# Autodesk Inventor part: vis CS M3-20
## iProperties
Shininess: 20.0
Angle Display Precision: 2
Document Length Units: 11269
Document Angle Units: 11279
Document Time Units: 11290
Document Mass Units: 11283
Document Length Units Precision: 3
Document Angle Units Precision: 2
Compacted: True
Created: 2002-04
Part Number: vis CS M3-20
Material: Par défaut
Document SubType Name: Modélisation
Designer: thchene
Density: 0.0
Volumn: 0.0
Area: 0.0
PropertySet Name: Model Information
Control State: 0
Master: False
Checked Out: False
Author: thchene
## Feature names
1. Révolution1 [Revolution]
2. Extrusion1
3. Chanfrein1 [Chamfer]
